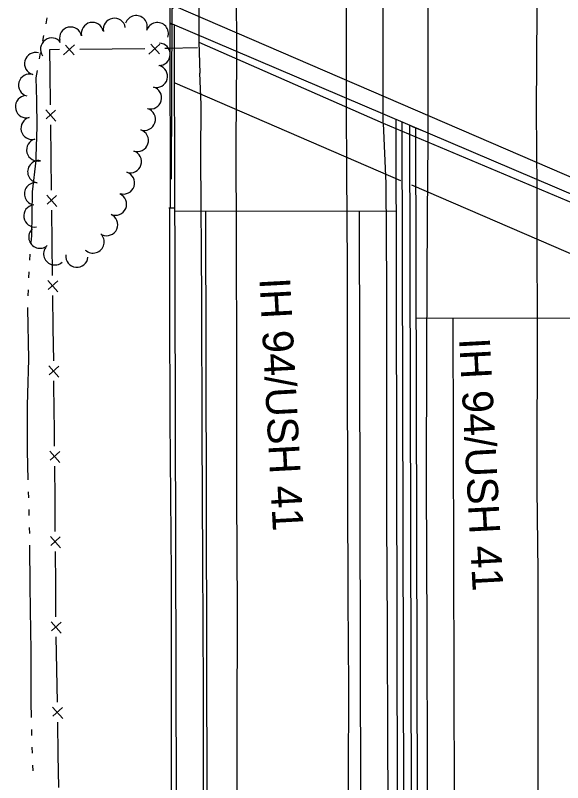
# Model space of a CAD drawing. Extents: x 588843 to 2552415, y 180129 to 269402.
# Drawn here: x 593887.8 to 594066, y 185185.1 to 185434.7 of the extents above; entities that cross this region are included whole.
import ezdxf

# ---------------------------------------------------------------- set-up
doc = ezdxf.new("R2010")
doc.units = 0
for name, color, linetype in [('E_FEN_P', 7, 'Continuous'), ('E_LAND_TreeLine_P', 7, 'Continuous'), ('E_RDWY', 7, 'Continuous'), ('E_RDWY_BarrierConc', 7, 'Continuous'), ('E_RDWY_Text', 7, 'Continuous'), ('E_STRUCT', 7, 'Continuous'), ('E_WTR_P', 7, 'Continuous'), ('P_RDWY_BarrierConc', 7, 'Continuous'), ('P_RDWY_PavtEdge', 7, 'Continuous'), ('P_RDWY_ShldPaved', 7, 'Continuous'), ('P_STRUCT', 7, 'Continuous')]:
    doc.layers.add(name, color=color, linetype=linetype)

msp = doc.modelspace()

# ---------------------------------------------------------------- linework, layer by layer
at = {"layer": 'E_FEN_P'}
for p, q in [((593934.86, 185425.38), (593931.2, 185422.13)), ((593907.11, 185425.11), (593903.45, 185421.86)), ((593906.97, 185421.89), (593904.16, 185425.01)), ((593934.73, 185422.17), (593931.92, 185425.29)), ((593897.68, 185403.97), (593900.94, 185400.32)), ((593900.9, 185403.84), (593897.78, 185401.02)), ((593898.02, 185376.21), (593901.28, 185372.56)), ((593901.24, 185376.09), (593898.13, 185373.27)), ((593898.37, 185348.46), (593901.63, 185344.81)), ((593901.58, 185348.33), (593898.47, 185345.52)), ((593898.71, 185320.71), (593901.97, 185317.06)), ((593901.92, 185320.58), (593898.81, 185317.76)), ((593899.01, 185292.96), (593902.25, 185289.29)), ((593902.23, 185292.82), (593899.1, 185290.01)), ((593899.22, 185265.21), (593902.46, 185261.54)), ((593902.43, 185265.06), (593899.3, 185262.26)), ((593899.45, 185237.44), (593902.73, 185233.8)), ((593902.67, 185237.32), (593899.57, 185234.49)), ((593899.93, 185209.68), (593903.21, 185206.05)), ((593903.15, 185209.57), (593900.05, 185206.74))]:
    msp.add_line(p, q, dxfattribs=at)
for points in [[(593902.19, 185423.57), (593898.92, 185423.54), (593899.01, 185416.21)], [(593919.35, 185423.75), (593908.75, 185423.64)], [(593929.95, 185423.85), (593919.35, 185423.75)], [(593947.1, 185424.11), (593937.48, 185423.93), (593936.51, 185423.92)], [(593899.01, 185416.21), (593899.15, 185405.62)], [(593899.23, 185399.06), (593899.36, 185388.46)], [(593899.36, 185388.46), (593899.49, 185377.86)], [(593899.57, 185371.3), (593899.7, 185360.71)], [(593899.7, 185360.71), (593899.83, 185350.11)], [(593899.91, 185343.55), (593900.04, 185332.95)], [(593900.04, 185332.95), (593900.17, 185322.36)], [(593900.25, 185315.8), (593900.38, 185305.2)], [(593900.38, 185305.2), (593900.43, 185301.11), (593900.48, 185294.6)], [(593900.53, 185288.04), (593900.61, 185277.44)], [(593900.61, 185277.44), (593900.69, 185266.85)], [(593900.74, 185260.29), (593900.82, 185249.69)], [(593900.82, 185249.69), (593900.89, 185240.29), (593900.91, 185239.09)], [(593901.02, 185232.53), (593901.2, 185221.94)], [(593901.2, 185221.94), (593901.39, 185211.34)], [(593901.5, 185204.78), (593901.68, 185194.19)], [(593901.68, 185194.19), (593901.86, 185183.59)]]:
    msp.add_lwpolyline(points, dxfattribs=at)
at = {"layer": 'E_LAND_TreeLine_P'}
for centre, start, end in [((593920.03, 185430.14), 10.4145, 190.4145), ((593927.13, 185431.01), 341.8642, 161.8642), ((593905.8, 185427.27), 12.1254, 192.1254), ((593912.89, 185428.8), 12.1254, 192.1254), ((593934.03, 185428.75), 341.8642, 161.8642), ((593899.62, 185423.71), 36.1686, 216.1686), ((593934.57, 185422.03), 268.2823, 88.2823), ((593894.4, 185418.99), 74.6652, 254.6652), ((593933.72, 185414.87), 254.5703, 74.5703), ((593892.48, 185411.99), 74.6652, 254.6652), ((593931.79, 185407.87), 254.5703, 74.5703), ((593891.43, 185404.99), 104.6713, 284.6713), ((593929.77, 185400.9), 251.7652, 71.7652), ((593893.26, 185397.96), 104.6713, 284.6713), ((593927.5, 185394.01), 251.7652, 71.7652), ((593895.1, 185390.94), 104.6713, 284.6713), ((593925.24, 185387.11), 251.9974, 71.9974), ((593895.42, 185383.84), 81.5633, 261.5633), ((593923, 185380.21), 251.9974, 71.9974), ((593894.36, 185376.66), 81.5633, 261.5633), ((593920.39, 185373.3), 246.449, 66.449), ((593894.17, 185369.48), 98.6414, 278.6414), ((593917.49, 185366.65), 246.449, 66.449), ((593895.8, 185362.56), 131.6659, 311.6659), ((593913.08, 185361), 226.4243, 46.4243), ((593900.62, 185357.14), 131.6659, 311.6659), ((593907.84, 185356.39), 174.135, 354.135)]:
    msp.add_arc(centre, 3.63, start, end, dxfattribs=at)
at = {"layer": 'E_RDWY'}
for points in [[(593959.87, 185420.54), (593959.84, 185445.18), (593959.68, 185484.05), (593959.45, 185518.19), (593959.33, 185553.9), (593959.27, 185602.1), (593959.3, 185642.07)], [(593995.63, 185404.88), (593995.6, 185440.77), (593995.74, 185473.91), (593995.68, 185502.41), (593995.72, 185538.18), (593995.67, 185568.02), (593995.66, 185604.47), (593995.5, 185626.87)], [(594022.14, 185393.45), (594022.21, 185425.91), (594022.13, 185466.23), (594022.08, 185503.34), (594021.81, 185547.03), (594021.91, 185590.06), (594021.79, 185615.43)], [(594057.68, 185378.51), (594057.47, 185403.68), (594057.63, 185436.51), (594057.67, 185474.34), (594057.7, 185515.46), (594057.58, 185553.57), (594057.6, 185599.99)], [(593960.11, 185156.58), (593960.05, 185202.8), (593960.09, 185241.65), (593959.88, 185278.24), (593959.89, 185323.37), (593959.78, 185360.75), (593959.65, 185393.32), (593959.87, 185420.54)], [(593996.36, 185155.17), (593996.3, 185186.28), (593996.32, 185216.24), (593996.09, 185244.79), (593996.03, 185281.16), (593995.91, 185318.32), (593995.88, 185353.01), (593995.73, 185384.05), (593995.63, 185404.88)], [(594023.34, 184682.26), (594023.25, 184709.56), (594023.04, 184739.91), (594023, 184778.2), (594022.82, 184818.16), (594022.67, 184861.06), (594022.65, 184896.86), (594022.58, 184934.07), (594022.62, 184972.8), (594022.48, 185013.2), (594022.39, 185057.62), (594022.2, 185103.22), (594022.12, 185147.96), (594021.99, 185189.79), (594021.86, 185234.19), (594021.61, 185282.87), (594021.71, 185325.21), (594022.01, 185370.2), (594022.14, 185393.45)], [(594058.92, 184785.01), (594058.82, 184814.32), (594058.74, 184856.48), (594058.72, 184888.42), (594058.64, 184920.39), (594058.61, 184955.57), (594058.47, 184990.54), (594058.38, 185026.41), (594058.18, 185063.12), (594058.32, 185096.32), (594058.13, 185129.63), (594058.04, 185158.77), (594058.03, 185187.99), (594057.99, 185226.54), (594057.97, 185253.66), (594057.64, 185280.67), (594057.82, 185338.96), (594057.67, 185356.32), (594057.68, 185378.51)]]:
    msp.add_lwpolyline(points, dxfattribs=at)
at = {"layer": 'E_RDWY_BarrierConc'}
msp.add_lwpolyline([(593937.96, 185372.16), (593938.03, 185339.45), (593938.08, 185303.3), (593938.5, 185252.99), (593938.55, 185202.16), (593938.47, 185154.12), (593938.23, 185123.59), (593938.78, 185094.92), (593938.68, 185047.47)], dxfattribs=at)
at = {"layer": 'E_STRUCT'}
for points in [[(593938.1, 185432.27), (594092.05, 185366.69), (594091.65, 185474.37), (594091.41, 185581.17), (593937.6, 185645.83)], [(593937.6, 185645.83), (593937.74, 185594.93), (593937.91, 185537.56), (593938.1, 185432.27)], [(593947.53, 185425.93), (594007.57, 185399.67), (594069.43, 185373.6), (594069.03, 185595.2), (594007.48, 185621.74), (593947.15, 185647.44), (593947.53, 185425.93)], [(594007.57, 185399.67), (594007.57, 185428.21), (594007.32, 185465.26), (594007.38, 185496.34), (594007.27, 185528.01), (594006.95, 185555.68), (594007.15, 185580.26), (594007.06, 185599.87), (594007.48, 185621.74)], [(593940.03, 185437.58), (593938.7, 185436.78), (593938.47, 185381.39)], [(593940.03, 185437.58), (594091.04, 185372.39), (594091.42, 185371.08), (594091.82, 185162.88), (594092.22, 184996.64), (594092.65, 184834.31), (594092.95, 184677.06)], [(593947.53, 185425.93), (593947.89, 185415.89)], [(593949.5, 184809.8), (593949.49, 184844.07), (593949.38, 184874.99), (593949.34, 184910.76), (593949.25, 184952.33), (593949.24, 184977.34), (593949.2, 185005.39), (593949.13, 185032.79), (593948.99, 185077.15), (593948.89, 185110.83), (593948.85, 185154.41), (593949.04, 185179.37), (593949.06, 185215.53), (593948.81, 185257.23), (593948.62, 185298.71), (593948.49, 185342.33), (593948.21, 185388.66), (593948.33, 185405.71), (593947.89, 185415.89)], [(594007.57, 185399.67), (594008.45, 185379.96), (594008.58, 185346.39), (594008.62, 185302.69), (594008.59, 185270.63), (594008.85, 185235.62), (594008.95, 185198.53), (594009.16, 185161.43), (594009.23, 185125.36), (594009.42, 185092.69), (594009.24, 185064.46), (594009.4, 185031), (594009.61, 184996.11), (594009.68, 184962.18), (594009.8, 184932.13), (594009.91, 184898.48), (594010.17, 184858.49), (594010.07, 184823.02), (594010.32, 184787.4), (594010.45, 184753.11), (594010.69, 184718.6), (594010.65, 184679.45), (594010.55, 184642.38), (594010.12, 184601.49)]]:
    msp.add_lwpolyline(points, dxfattribs=at)
at = {"layer": 'E_WTR_P'}
for points in [[(593898.05, 185433.87), (593897.7, 185431.97)], [(593896.98, 185428.17), (593896.63, 185426.27)], [(593895.91, 185422.47), (593895.55, 185420.57)], [(593894.86, 185416.77), (593894.43, 185414.43), (593894.71, 185407.03), (593894.85, 185398.49), (593894.47, 185388.81)], [(593894.47, 185388.81), (593894.42, 185387.46), (593893.33, 185377.34), (593893.07, 185362.94), (593892.89, 185360.86)], [(593892.56, 185357.01), (593892.4, 185355.09)], [(593892.15, 185351.23), (593892.09, 185349.3)], [(593891.98, 185345.44), (593891.92, 185343.5)], [(593891.81, 185339.64), (593891.8, 185339.36), (593892.06, 185322.9), (593891.79, 185311.63)], [(593891.79, 185311.63), (593891.69, 185307.76), (593891.65, 185293.03), (593891.92, 185283.62)], [(593892.02, 185279.75), (593892.08, 185277.82)], [(593892.19, 185273.96), (593892.24, 185272.02)], [(593892.34, 185268.16), (593892.36, 185266.23)], [(593892.4, 185262.36), (593892.53, 185249.05), (593892.76, 185234.35)], [(593892.76, 185234.35), (593892.85, 185228.43), (593892.79, 185211.2), (593892.92, 185206.33)], [(593893.03, 185202.47), (593893.08, 185200.53)], [(593893.19, 185196.67), (593893.24, 185194.74)], [(593893.35, 185190.88), (593893.45, 185188.95)]]:
    msp.add_lwpolyline(points, dxfattribs=at)
at = {"layer": 'P_RDWY_BarrierConc'}
for p, q in [((594015.52, 183703.15), (594011.71, 185400.89)), ((594017.52, 183703.15), (594013.71, 185400.03)), ((594020.02, 183703.16), (594016.21, 185398.95)), ((594022.02, 183703.16), (594018.21, 185398.08)), ((593941.13, 184768.81), (593939.74, 185387.02)), ((593939.77, 185372.02), (593937.77, 185372.01))]:
    msp.add_line(p, q, dxfattribs=at)
at = {"layer": 'P_RDWY_PavtEdge'}
for p, q in [((593939.78, 185371.01), (594011.77, 185371.17)), ((594003.52, 183703.12), (593999.78, 185371.14)), ((594018.35, 185336.21), (594090.35, 185336.37)), ((594034.02, 183703.19), (594030.35, 185336.23))]:
    msp.add_line(p, q, dxfattribs=at)
at = {"layer": 'P_RDWY_ShldPaved'}
msp.add_line((593951.77, 184483.94), (593949.78, 185371.03), dxfattribs=at)
at = {"layer": 'P_STRUCT'}
for p, q in [((593938.19, 185431.88), (593938.19, 185432.23)), ((593938.32, 185372.02), (593938.19, 185431.88)), ((593939, 185431.88), (593938.19, 185431.88)), ((593939.77, 185372.02), (593939.64, 185431.61)), ((593939.68, 185412.74), (594013.2, 185380.99)), ((594016.77, 185398.71), (594020.22, 185397.22)), ((594018.21, 185398.08), (594018.21, 185398.14)), ((594090.33, 185347.69), (594016.81, 185379.44))]:
    msp.add_line(p, q, dxfattribs=at)

# ---------------------------------------------------------------- texts
at = {"layer": 'E_RDWY_Text'}
for p in [(593967.22, 185349.12), (594032.25, 185329.57)]:
    msp.add_text('IH 94/USH 41', height=10, rotation=273.0955, dxfattribs=at).set_placement(p)

doc.saveas('drawing.dxf')
